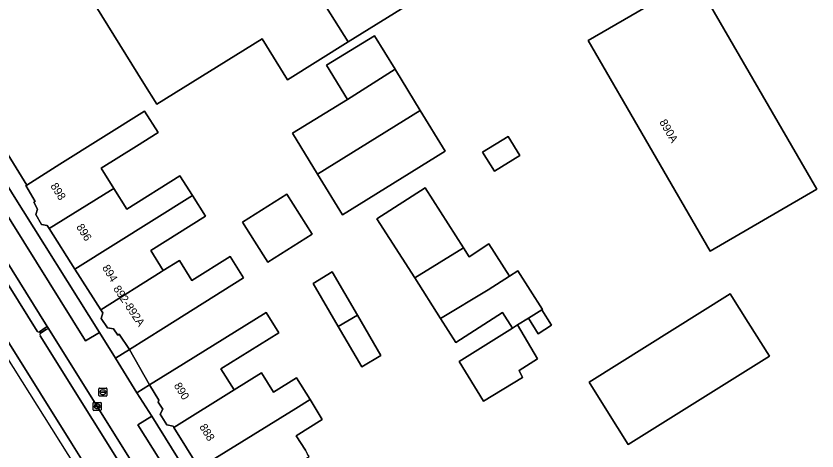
# Model space of a CAD drawing. Extents: x 158455 to 159797, y 387218 to 388672.
# Drawn here: x 158785.4 to 158885.4, y 387285.9 to 387340.2 of the extents above; entities that cross this region are included whole.
import ezdxf

# ---------------------------------------------------------------- set-up
doc = ezdxf.new("R2010")
doc.units = 0
for name, color, linetype in [('IMGEO_Berm_groen', 7, 'Continuous'), ('IMGEO_Erf', 7, 'Continuous'), ('IMGEO_Groenvoorziening', 7, 'Continuous'), ('IMGEO_Haag', 7, 'Continuous'), ('IMGEO_Kolk', 7, 'Continuous'), ('IMGEO_Pand', 7, 'Continuous'), ('IMGEO_Pand_nummerreeks', 7, 'Continuous'), ('IMGEO_Parkeervlak_open', 7, 'Continuous'), ('IMGEO_Rijbaan_lokaal_open', 7, 'Continuous'), ('IMGEO_Rijbaan_regionaal_gesloten', 7, 'Continuous'), ('IMGEO_Rioolput', 7, 'Continuous'), ('IMGEO_Terreindeel_gesloten', 7, 'Continuous'), ('IMGEO_Voetpad_open', 7, 'Continuous')]:
    doc.layers.add(name, color=color, linetype=linetype)

msp = doc.modelspace()

# ---------------------------------------------------------------- linework, layer by layer
at = {"layer": 'IMGEO_Berm_groen'}
for points in [[(158788.33, 387300.8), (158789.07, 387301.31), (158789.31, 387301.47), (158783.19, 387311.27), (158776.12, 387322.71)], [(158774.99, 387321.85), (158788.06, 387300.91)]]:
    msp.add_lwpolyline(points, dxfattribs=at)
msp.add_arc((158788.28, 387301.09), 0.288, 218.9073, 278.5295, dxfattribs=at)
at = {"layer": 'IMGEO_Erf'}
for points in [[(158831.8, 387347.72), (158835.24, 387342.31), (158835.3, 387342.21), (158826.9, 387337), (158819.32, 387332.29), (158816.14, 387337.41), (158802.98, 387329.24), (158801.39, 387331.8), (158793.87, 387343.92), (158790.47, 387349.36), (158812.74, 387377.68)], [(158885.44, 387318.61), (158872.12, 387310.88), (158856.86, 387337.18), (158870.18, 387344.91)], [(158839, 387323.39), (158826.18, 387315.42), (158823.08, 387320.48), (158819.93, 387325.62), (158826.81, 387329.84), (158824.2, 387334.11), (158830.2, 387337.78), (158832.76, 387333.6), (158832.81, 387333.51), (158835.9, 387328.46)], [(158848.32, 387322.81), (158845.15, 387320.87), (158843.69, 387323.25), (158846.86, 387325.19)], [(158852.3, 387301.66), (158850.63, 387300.58), (158849.42, 387302.53), (158848.04, 387301.67), (158850.52, 387297.44), (158848.23, 387295.99), (158848.66, 387295.12), (158843.8, 387292.17), (158840.77, 387297.12), (158847.43, 387301.29), (158846.18, 387303.23), (158840.34, 387299.5), (158838.44, 387302.48), (158835.21, 387307.54), (158830.48, 387314.94), (158836.5, 387318.79), (158841.28, 387311.3), (158841.99, 387310.2), (158844.48, 387311.79), (158847.06, 387307.76), (158848.1, 387308.42), (158851.17, 387303.62), (158851.07, 387303.56)], [(158816.88, 387309.51), (158815.21, 387312.15), (158813.71, 387314.51), (158819.22, 387318.01), (158822.4, 387313)], [(158830.99, 387297.85), (158828.59, 387296.46), (158825.65, 387301.5), (158822.52, 387306.86), (158824.88, 387308.32), (158828.04, 387302.9)], [(158874.61, 387305.57), (158876.84, 387302), (158879.49, 387297.76), (158861.85, 387286.74), (158859.2, 387290.98), (158856.97, 387294.54)]]:
    msp.add_lwpolyline(points, close=True, dxfattribs=at)
msp.add_lwpolyline([(158780.72, 387328.86), (158786.75, 387319.14), (158790.89, 387321.74), (158801.46, 387328.37), (158803.15, 387325.69), (158800.46, 387324.01), (158796.06, 387321.25), (158797.65, 387318.72), (158799.26, 387316.15), (158805.89, 387320.31), (158807.45, 387317.84), (158809.06, 387315.26), (158802.24, 387310.98), (158803.81, 387308.47), (158805.83, 387309.74), (158807.39, 387307.24), (158812.14, 387310.22), (158813.82, 387307.55), (158803.82, 387301.28), (158799.59, 387298.62), (158802.07, 387294.18), (158806.32, 387296.82), (158816.65, 387303.23), (158818.23, 387300.69), (158811.01, 387296.21), (158812.66, 387293.56), (158816.08, 387295.68), (158817.58, 387293.28), (158820.45, 387295.06), (158822.13, 387292.35), (158823.66, 387289.87), (158820.41, 387287.85), (158821.55, 387286.03), (158821.83, 387285.56)], dxfattribs=at)
at = {"layer": 'IMGEO_Groenvoorziening'}
for points in [[(158789.45, 387301.25), (158789.2, 387301.1), (158788.47, 387300.63)], [(158815.23, 387257.71), (158815.99, 387258.22), (158816.25, 387258.39), (158813.52, 387262.75), (158811.96, 387265.28), (158808.96, 387270.1), (158807.32, 387272.63), (158789.45, 387301.25)], [(158788.43, 387300.33), (158801.51, 387279.44)]]:
    msp.add_lwpolyline(points, dxfattribs=at)
msp.add_arc((158788.68, 387300.45), 0.277, 137.8923, 205.2675, dxfattribs=at)
at = {"layer": 'IMGEO_Haag'}
for points in [[(158789.45, 387301.25), (158789.2, 387301.1), (158788.47, 387300.63)], [(158815.23, 387257.71), (158815.99, 387258.22), (158816.25, 387258.39), (158813.52, 387262.75), (158811.96, 387265.28), (158808.96, 387270.1), (158807.32, 387272.63), (158789.45, 387301.25)], [(158788.43, 387300.33), (158801.51, 387279.44)]]:
    msp.add_lwpolyline(points, dxfattribs=at)
msp.add_arc((158788.68, 387300.45), 0.277, 137.8923, 205.2675, dxfattribs=at)
at = {"layer": 'IMGEO_Kolk'}
for p, q in [((158795.12, 387292.01), (158795.98, 387292.01)), ((158795.05, 387291.09), (158795.05, 387291.94)), ((158795.98, 387291.01), (158795.12, 387291.01)), ((158795.31, 387291.51), (158795.31, 387291.52)), ((158795.35, 387291.56), (158795.75, 387291.56)), ((158795.74, 387291.47), (158795.35, 387291.47)), ((158795.56, 387291.23), (158795.53, 387291.23)), ((158795.54, 387291.79), (158795.56, 387291.79)), ((158795.79, 387291.52), (158795.79, 387291.51)), ((158796.05, 387291.94), (158796.05, 387291.09))]:
    msp.add_line(p, q, dxfattribs=at)
for points in [[(158795.12, 387292.01), (158795.98, 387292.01)], [(158795.05, 387291.09), (158795.05, 387291.94)], [(158795.98, 387291.01), (158795.12, 387291.01)], [(158796.05, 387291.94), (158796.05, 387291.09)]]:
    msp.add_lwpolyline(points, dxfattribs=at)
for centre, radius, start, end in [((158795.12, 387291.94), 0.0765, 91.552, 178.448), ((158795.12, 387291.94), 0.0765, 91.552, 178.448), ((158795.97, 387291.94), 0.0765, 1.552, 88.448), ((158795.97, 387291.94), 0.0765, 1.552, 88.448), ((158795.12, 387291.09), 0.0765, 181.552, 268.448), ((158795.12, 387291.09), 0.0765, 181.552, 268.448), ((158795.35, 387291.52), 0.0403, 85.8775, 175.7526), ((158795.34, 387291.51), 0.0366, 178.938, 274.7102), ((158795.75, 387291.51), 0.043, 264.8664, 352.4533), ((158795.75, 387291.52), 0.0386, 1.7309, 96.639), ((158795.97, 387291.09), 0.0765, 271.552, 358.448), ((158795.97, 387291.09), 0.0765, 271.552, 358.448)]:
    msp.add_arc(centre, radius, start, end, dxfattribs=at)
for centre, major_axis, ratio, start_param, end_param in [((158795.54, 387291.51), (-0.387, 0.002), 0.722429, 4.712389, 7.853982), ((158795.56, 387291.51), (-0.39, 0.002), 0.717154, 1.570796, 4.712389)]:
    msp.add_ellipse(centre, major_axis=major_axis, ratio=ratio, start_param=start_param, end_param=end_param, dxfattribs=at)
at = {"layer": 'IMGEO_Pand'}
for points in [[(158831.8, 387347.72), (158812.74, 387377.68), (158790.47, 387349.36), (158793.87, 387343.92), (158801.39, 387331.8), (158802.98, 387329.24), (158816.14, 387337.41), (158819.32, 387332.29), (158826.9, 387337), (158823.46, 387342.49)], [(158831.8, 387347.72), (158823.46, 387342.49), (158826.9, 387337), (158835.3, 387342.21), (158835.24, 387342.31)], [(158872.12, 387310.88), (158885.44, 387318.61), (158870.18, 387344.91), (158856.86, 387337.18)], [(158832.76, 387333.6), (158830.2, 387337.78), (158824.2, 387334.11), (158826.81, 387329.84)], [(158832.76, 387333.6), (158826.81, 387329.84), (158819.93, 387325.62), (158823.08, 387320.48), (158835.9, 387328.46), (158832.81, 387333.51)], [(158797.65, 387318.72), (158796.06, 387321.25), (158800.46, 387324.01), (158803.15, 387325.69), (158801.46, 387328.37), (158790.89, 387321.74), (158786.75, 387319.14), (158786.66, 387319.08), (158787.81, 387317.1), (158787.62, 387316.99), (158788.11, 387316.14), (158787.88, 387315.46), (158788.59, 387314.22), (158789.3, 387314.09), (158789.55, 387313.7), (158797.22, 387318.46)], [(158835.9, 387328.46), (158823.08, 387320.48), (158826.18, 387315.42), (158839, 387323.39)], [(158843.69, 387323.25), (158845.15, 387320.87), (158848.32, 387322.81), (158846.86, 387325.19)], [(158792.77, 387308.63), (158807.45, 387317.84), (158805.89, 387320.31), (158799.26, 387316.15), (158797.65, 387318.72), (158797.22, 387318.46), (158789.55, 387313.7)], [(158835.21, 387307.54), (158841.28, 387311.3), (158836.5, 387318.79), (158830.48, 387314.94)], [(158792.77, 387308.63), (158795.99, 387303.57), (158803.56, 387308.32), (158803.81, 387308.47), (158802.24, 387310.98), (158809.06, 387315.26), (158807.45, 387317.84)], [(158822.4, 387313), (158819.22, 387318.01), (158813.71, 387314.51), (158815.21, 387312.15), (158816.88, 387309.51)], [(158835.21, 387307.54), (158838.44, 387302.48), (158844.39, 387306.05), (158847.06, 387307.76), (158844.48, 387311.79), (158841.99, 387310.2), (158841.28, 387311.3)], [(158813.82, 387307.55), (158812.14, 387310.22), (158807.39, 387307.24), (158805.83, 387309.74), (158803.81, 387308.47), (158803.56, 387308.32), (158795.99, 387303.57), (158796.24, 387303.18), (158796.05, 387302.48), (158796.85, 387301.3), (158797.57, 387301.21), (158798.12, 387300.39), (158798.3, 387300.52), (158799.59, 387298.62), (158803.82, 387301.28)], [(158825.65, 387301.5), (158828.04, 387302.9), (158824.88, 387308.32), (158822.52, 387306.86)], [(158846.18, 387303.23), (158847.43, 387301.29), (158848.04, 387301.67), (158849.42, 387302.53), (158851.07, 387303.56), (158851.17, 387303.62), (158848.1, 387308.42), (158847.06, 387307.76), (158844.39, 387306.05), (158838.44, 387302.48), (158840.34, 387299.5)], [(158876.84, 387302), (158874.61, 387305.57), (158856.97, 387294.54), (158859.2, 387290.98), (158861.85, 387286.74), (158879.49, 387297.76)], [(158812.66, 387293.56), (158811.01, 387296.21), (158818.23, 387300.69), (158816.65, 387303.23), (158806.32, 387296.82), (158802.07, 387294.18), (158803.24, 387292.3), (158803.18, 387292.04), (158803.74, 387291.15), (158803.42, 387290.55), (158804.25, 387289.22), (158805.03, 387289.03), (158805.12, 387288.88)], [(158851.07, 387303.56), (158849.42, 387302.53), (158850.63, 387300.58), (158852.3, 387301.66)], [(158825.65, 387301.5), (158828.59, 387296.46), (158830.99, 387297.85), (158828.04, 387302.9)], [(158850.52, 387297.44), (158848.04, 387301.67), (158847.43, 387301.29), (158840.77, 387297.12), (158843.8, 387292.17), (158848.66, 387295.12), (158848.23, 387295.99)], [(158820.34, 387291.26), (158822.13, 387292.35), (158820.45, 387295.06), (158817.58, 387293.28), (158816.08, 387295.68), (158812.66, 387293.56), (158805.12, 387288.88), (158808.29, 387283.78)], [(158823.66, 387289.87), (158822.13, 387292.35), (158820.34, 387291.26), (158808.29, 387283.78), (158811.45, 387278.68), (158819.03, 387283.39), (158821.33, 387284.81), (158822.03, 387285.25), (158821.83, 387285.56), (158821.55, 387286.03), (158820.41, 387287.85)]]:
    msp.add_lwpolyline(points, close=True, dxfattribs=at)
at = {"layer": 'IMGEO_Parkeervlak_open'}
for points in [[(158780.38, 387325.48), (158778.66, 387324.41), (158794.08, 387299.69), (158795.82, 387300.75), (158784.97, 387318.04)], [(158802.36, 387290.27), (158800.64, 387289.21), (158809.98, 387274.3), (158811.66, 387275.36)]]:
    msp.add_lwpolyline(points, close=True, dxfattribs=at)
at = {"layer": 'IMGEO_Rijbaan_lokaal_open'}
msp.add_lwpolyline([(158763.16, 387343.53), (158771.83, 387329.65), (158776, 387322.91), (158776.12, 387322.71), (158783.19, 387311.27), (158789.31, 387301.47), (158789.45, 387301.25), (158807.32, 387272.63), (158809.98, 387274.3), (158800.64, 387289.21), (158802.36, 387290.27), (158800.52, 387293.22), (158797.83, 387297.52), (158795.82, 387300.75), (158794.08, 387299.69), (158778.66, 387324.41), (158780.38, 387325.48), (158778.94, 387327.79), (158775.37, 387333.47), (158774.4, 387335), (158770.1, 387341.85)], dxfattribs=at)
at = {"layer": 'IMGEO_Rijbaan_regionaal_gesloten'}
for points in [[(158588.04, 387615.09), (158677.18, 387467.99), (158823.36, 387235.46), (158823.44, 387235.51), (158824.18, 387235.99), (158792.36, 387286.93), (158694.26, 387443.97), (158684.57, 387459.46), (158661.98, 387495.7), (158658.09, 387501.91), (158642.29, 387527.16), (158630.02, 387546.72), (158625.56, 387554.19)], [(158625.56, 387554.19), (158630.02, 387546.72), (158642.29, 387527.16), (158658.09, 387501.91), (158661.98, 387495.7), (158684.57, 387459.46), (158694.26, 387443.97), (158792.36, 387286.93), (158824.18, 387235.99), (158827.38, 387238.07), (158819.16, 387251.21), (158817.46, 387253.85), (158817.39, 387253.96), (158815.34, 387257.19)], [(158788.06, 387300.91), (158774.99, 387321.85)], [(158788.47, 387300.63), (158788.33, 387300.8)], [(158801.51, 387279.44), (158788.43, 387300.33)]]:
    msp.add_lwpolyline(points, dxfattribs=at)
for centre, radius, start, end in [((158788.28, 387301.09), 0.288, 218.9073, 278.5295), ((158788.68, 387300.45), 0.277, 137.8923, 205.2675)]:
    msp.add_arc(centre, radius, start, end, dxfattribs=at)
at = {"layer": 'IMGEO_Rioolput'}
for p, q in [((158795.76, 387292.86), (158795.76, 387293.71)), ((158795.84, 387293.78), (158796.69, 387293.78)), ((158796.02, 387293.28), (158796.02, 387293.29)), ((158796.46, 387293.24), (158796.06, 387293.24)), ((158796.07, 387293.33), (158796.46, 387293.33)), ((158796.25, 387293.56), (158796.28, 387293.56)), ((158796.51, 387293.29), (158796.51, 387293.28)), ((158796.76, 387293.71), (158796.76, 387292.86)), ((158796.69, 387292.78), (158795.84, 387292.78)), ((158796.27, 387293), (158796.25, 387293))]:
    msp.add_line(p, q, dxfattribs=at)
for points in [[(158795.76, 387292.86), (158795.76, 387293.71)], [(158795.84, 387293.78), (158796.69, 387293.78)], [(158796.76, 387293.71), (158796.76, 387292.86)], [(158796.69, 387292.78), (158795.84, 387292.78)]]:
    msp.add_lwpolyline(points, dxfattribs=at)
for centre, radius, start, end in [((158795.84, 387293.71), 0.0765, 91.552, 178.448), ((158795.84, 387293.71), 0.0765, 91.552, 178.448), ((158796.06, 387293.29), 0.0403, 85.8775, 175.7526), ((158796.06, 387293.28), 0.0366, 178.938, 274.7102), ((158796.47, 387293.29), 0.0386, 1.7309, 96.639), ((158796.46, 387293.28), 0.043, 264.8664, 352.4533), ((158796.69, 387293.71), 0.0765, 1.552, 88.448), ((158796.69, 387293.71), 0.0765, 1.552, 88.448), ((158795.84, 387292.86), 0.0765, 181.552, 268.448), ((158795.84, 387292.86), 0.0765, 181.552, 268.448), ((158796.69, 387292.86), 0.0765, 271.552, 358.448), ((158796.69, 387292.86), 0.0765, 271.552, 358.448)]:
    msp.add_arc(centre, radius, start, end, dxfattribs=at)
for centre, major_axis, ratio, start_param, end_param in [((158796.25, 387293.28), (-0.387, 0.002), 0.722429, 4.712389, 7.853982), ((158796.27, 387293.28), (-0.39, 0.002), 0.717154, 1.570796, 4.712389)]:
    msp.add_ellipse(centre, major_axis=major_axis, ratio=ratio, start_param=start_param, end_param=end_param, dxfattribs=at)
at = {"layer": 'IMGEO_Terreindeel_gesloten'}
msp.add_lwpolyline([(158789.2, 387301.1), (158789.45, 387301.25), (158789.31, 387301.47), (158789.07, 387301.31), (158788.33, 387300.8), (158788.47, 387300.63)], close=True, dxfattribs=at)
at = {"layer": 'IMGEO_Voetpad_open'}
for points in [[(158784.97, 387318.04), (158795.82, 387300.75), (158797.83, 387297.52), (158799.59, 387298.62), (158798.3, 387300.52), (158798.12, 387300.39), (158797.57, 387301.21), (158796.85, 387301.3), (158796.05, 387302.48), (158796.24, 387303.18), (158795.99, 387303.57), (158792.77, 387308.63), (158789.55, 387313.7), (158789.3, 387314.09), (158788.59, 387314.22), (158787.88, 387315.46), (158788.11, 387316.14), (158787.62, 387316.99), (158787.81, 387317.1), (158786.66, 387319.08), (158786.75, 387319.14), (158780.72, 387328.86), (158778.94, 387327.79), (158780.38, 387325.48)], [(158800.52, 387293.22), (158802.07, 387294.18), (158799.59, 387298.62), (158797.83, 387297.52)], [(158802.36, 387290.27), (158811.66, 387275.36), (158813.27, 387272.82), (158813.33, 387272.72), (158814.82, 387273.6), (158813.69, 387275.42), (158813.39, 387275.49), (158812.95, 387276.2), (158812.13, 387276.4), (158811.44, 387277.5), (158811.64, 387278.37), (158811.45, 387278.68), (158808.29, 387283.78), (158805.12, 387288.88), (158805.03, 387289.03), (158804.25, 387289.22), (158803.42, 387290.55), (158803.74, 387291.15), (158803.18, 387292.04), (158803.24, 387292.3), (158802.07, 387294.18), (158800.52, 387293.22)]]:
    msp.add_lwpolyline(points, close=True, dxfattribs=at)

# ---------------------------------------------------------------- texts
at = {"layer": 'IMGEO_Pand_nummerreeks'}
for s, rotation, p in [('890A', 300.1587, (158865.72, 387327)), ('898', 302.2909, (158789.67, 387319.03)), ('896', 302.2909, (158792.9, 387313.92)), ('894', 302.2909, (158796.13, 387308.81)), ('892-892A', 304.108, (158797.5, 387306.19)), ('890', 301.7604, (158805.09, 387294.11)), ('888', 301.7588, (158808.27, 387288.96))]:
    msp.add_text(s, height=1, rotation=rotation, dxfattribs=at).set_placement(p)

doc.saveas('drawing.dxf')
